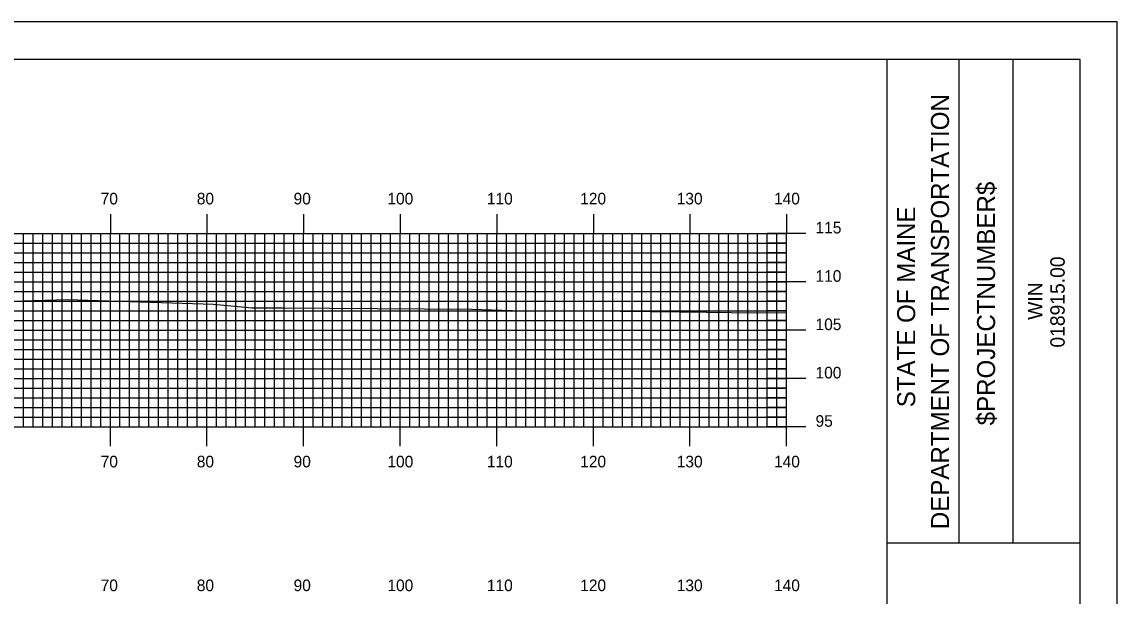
# Model space of a CAD drawing. Extents: x 1779106 to 1779449, y 442591 to 442811.
# Drawn here: x 1779332.2 to 1779445.5, y 442751.2 to 442810.5 of the extents above; entities that cross this region are included whole.
import ezdxf

# ---------------------------------------------------------------- set-up
doc = ezdxf.new("R2010")
doc.units = 0
for name, color, linetype in [('BORDER', 7, 'Continuous'), ('H_V ANNOTATION', 7, 'Continuous'), ('MAJOR', 7, 'Continuous'), ('MINOR', 7, 'Continuous'), ('PLOT BOUNDARY', 7, 'Continuous'), ('S_Roadway_Centerline', 7, 'Continuous')]:
    doc.layers.add(name, color=color, linetype=linetype)

msp = doc.modelspace()

# ---------------------------------------------------------------- linework, layer by layer
at = {"layer": 'BORDER'}
for p, q in [((1779421.73, 442596.67), (1779421.73, 442806.67)), ((1779429.19, 442756.66), (1779429.19, 442806.66)), ((1779434.78, 442756.66), (1779434.78, 442806.66)), ((1779421.73, 442756.65), (1779441.73, 442756.65))]:
    msp.add_line(p, q, dxfattribs=at)
msp.add_lwpolyline([(1779121.73, 442596.67), (1779441.73, 442596.67), (1779441.73, 442806.67), (1779121.73, 442806.67)], close=True, dxfattribs=at)
at = {"layer": 'MAJOR'}
for p, q in [((1779341.33, 442790.67), (1779341.33, 442788.67)), ((1779351.33, 442790.67), (1779351.33, 442788.67)), ((1779361.33, 442790.67), (1779361.33, 442788.67)), ((1779371.33, 442790.67), (1779371.33, 442788.67)), ((1779381.33, 442790.67), (1779381.33, 442788.67)), ((1779391.33, 442790.67), (1779391.33, 442788.67)), ((1779401.33, 442790.67), (1779401.33, 442788.67)), ((1779411.33, 442790.67), (1779411.33, 442788.67)), ((1779131.33, 442788.67), (1779411.33, 442788.67)), ((1779131.33, 442788.67), (1779411.33, 442788.67)), ((1779341.33, 442768.67), (1779341.33, 442788.67)), ((1779351.33, 442768.67), (1779351.33, 442788.67)), ((1779361.33, 442768.67), (1779361.33, 442788.67)), ((1779371.33, 442768.67), (1779371.33, 442788.67)), ((1779381.33, 442768.67), (1779381.33, 442788.67)), ((1779391.33, 442768.67), (1779391.33, 442788.67)), ((1779401.33, 442768.67), (1779401.33, 442788.67)), ((1779413.33, 442788.67), (1779409.33, 442788.67)), ((1779411.33, 442768.67), (1779411.33, 442788.67)), ((1779411.33, 442768.67), (1779411.33, 442788.67)), ((1779131.33, 442783.67), (1779411.33, 442783.67)), ((1779413.33, 442783.67), (1779409.33, 442783.67)), ((1779131.33, 442778.67), (1779411.33, 442778.67)), ((1779413.33, 442778.67), (1779409.33, 442778.67)), ((1779131.33, 442773.67), (1779411.33, 442773.67)), ((1779413.33, 442773.67), (1779409.33, 442773.67)), ((1779131.33, 442768.67), (1779411.33, 442768.67)), ((1779131.33, 442768.67), (1779411.33, 442768.67)), ((1779341.33, 442766.66), (1779341.33, 442768.67)), ((1779351.33, 442766.66), (1779351.33, 442768.67)), ((1779361.33, 442766.66), (1779361.33, 442768.67)), ((1779371.33, 442766.66), (1779371.33, 442768.67)), ((1779381.33, 442766.66), (1779381.33, 442768.67)), ((1779391.33, 442766.66), (1779391.33, 442768.67)), ((1779401.33, 442766.66), (1779401.33, 442768.67)), ((1779413.33, 442768.67), (1779409.33, 442768.67)), ((1779411.33, 442766.66), (1779411.33, 442768.67))]:
    msp.add_line(p, q, dxfattribs=at)
at = {"layer": 'MINOR'}
for p, q in [((1779332.33, 442768.67), (1779332.33, 442788.67)), ((1779333.33, 442768.67), (1779333.33, 442788.67)), ((1779334.33, 442768.67), (1779334.33, 442788.67)), ((1779335.33, 442768.67), (1779335.33, 442788.67)), ((1779336.33, 442768.67), (1779336.33, 442788.67)), ((1779337.33, 442768.67), (1779337.33, 442788.67)), ((1779338.33, 442768.67), (1779338.33, 442788.67)), ((1779339.33, 442768.67), (1779339.33, 442788.67)), ((1779340.33, 442768.67), (1779340.33, 442788.67)), ((1779342.33, 442768.67), (1779342.33, 442788.67)), ((1779343.33, 442768.67), (1779343.33, 442788.67)), ((1779344.33, 442768.67), (1779344.33, 442788.67)), ((1779345.33, 442768.67), (1779345.33, 442788.67)), ((1779346.33, 442768.67), (1779346.33, 442788.67)), ((1779347.33, 442768.67), (1779347.33, 442788.67)), ((1779348.33, 442768.67), (1779348.33, 442788.67)), ((1779349.33, 442768.67), (1779349.33, 442788.67)), ((1779350.33, 442768.67), (1779350.33, 442788.67)), ((1779352.33, 442768.67), (1779352.33, 442788.67)), ((1779353.33, 442768.67), (1779353.33, 442788.67)), ((1779354.33, 442768.67), (1779354.33, 442788.67)), ((1779355.33, 442768.67), (1779355.33, 442788.67)), ((1779356.33, 442768.67), (1779356.33, 442788.67)), ((1779357.33, 442768.67), (1779357.33, 442788.67)), ((1779358.33, 442768.67), (1779358.33, 442788.67)), ((1779359.33, 442768.67), (1779359.33, 442788.67)), ((1779360.33, 442768.67), (1779360.33, 442788.67)), ((1779362.33, 442768.67), (1779362.33, 442788.67)), ((1779363.33, 442768.67), (1779363.33, 442788.67)), ((1779364.33, 442768.67), (1779364.33, 442788.67)), ((1779365.33, 442768.67), (1779365.33, 442788.67)), ((1779366.33, 442768.67), (1779366.33, 442788.67)), ((1779367.33, 442768.67), (1779367.33, 442788.67)), ((1779368.33, 442768.67), (1779368.33, 442788.67)), ((1779369.33, 442768.67), (1779369.33, 442788.67)), ((1779370.33, 442768.67), (1779370.33, 442788.67)), ((1779372.33, 442768.67), (1779372.33, 442788.67)), ((1779373.33, 442768.67), (1779373.33, 442788.67)), ((1779374.33, 442768.67), (1779374.33, 442788.67)), ((1779375.33, 442768.67), (1779375.33, 442788.67)), ((1779376.33, 442768.67), (1779376.33, 442788.67)), ((1779377.33, 442768.67), (1779377.33, 442788.67)), ((1779378.33, 442768.67), (1779378.33, 442788.67)), ((1779379.33, 442768.67), (1779379.33, 442788.67)), ((1779380.33, 442768.67), (1779380.33, 442788.67)), ((1779382.33, 442768.67), (1779382.33, 442788.67)), ((1779383.33, 442768.67), (1779383.33, 442788.67)), ((1779384.33, 442768.67), (1779384.33, 442788.67)), ((1779385.33, 442768.67), (1779385.33, 442788.67)), ((1779386.33, 442768.67), (1779386.33, 442788.67)), ((1779387.33, 442768.67), (1779387.33, 442788.67)), ((1779388.33, 442768.67), (1779388.33, 442788.67)), ((1779389.33, 442768.67), (1779389.33, 442788.67)), ((1779390.33, 442768.67), (1779390.33, 442788.67)), ((1779392.33, 442768.67), (1779392.33, 442788.67)), ((1779393.33, 442768.67), (1779393.33, 442788.67)), ((1779394.33, 442768.67), (1779394.33, 442788.67)), ((1779395.33, 442768.67), (1779395.33, 442788.67)), ((1779396.33, 442768.67), (1779396.33, 442788.67)), ((1779397.33, 442768.67), (1779397.33, 442788.67)), ((1779398.33, 442768.67), (1779398.33, 442788.67)), ((1779399.33, 442768.67), (1779399.33, 442788.67)), ((1779400.33, 442768.67), (1779400.33, 442788.67)), ((1779402.33, 442768.67), (1779402.33, 442788.67)), ((1779403.33, 442768.67), (1779403.33, 442788.67)), ((1779404.33, 442768.67), (1779404.33, 442788.67)), ((1779405.33, 442768.67), (1779405.33, 442788.67)), ((1779406.33, 442768.67), (1779406.33, 442788.67)), ((1779407.33, 442768.67), (1779407.33, 442788.67)), ((1779408.33, 442768.67), (1779408.33, 442788.67)), ((1779409.33, 442768.67), (1779409.33, 442788.67)), ((1779410.33, 442768.67), (1779410.33, 442788.67)), ((1779131.33, 442787.67), (1779411.33, 442787.67)), ((1779411.33, 442787.67), (1779409.33, 442787.67)), ((1779131.33, 442786.67), (1779411.33, 442786.67)), ((1779411.33, 442786.67), (1779409.33, 442786.67)), ((1779131.33, 442785.67), (1779411.33, 442785.67)), ((1779411.33, 442785.67), (1779409.33, 442785.67)), ((1779131.33, 442784.67), (1779411.33, 442784.67)), ((1779411.33, 442784.67), (1779409.33, 442784.67)), ((1779131.33, 442782.67), (1779411.33, 442782.67)), ((1779411.33, 442782.67), (1779409.33, 442782.67)), ((1779131.33, 442781.67), (1779411.33, 442781.67)), ((1779131.33, 442780.67), (1779411.33, 442780.67)), ((1779411.33, 442781.67), (1779409.33, 442781.67)), ((1779411.33, 442780.67), (1779409.33, 442780.67)), ((1779131.33, 442779.67), (1779411.33, 442779.67)), ((1779411.33, 442779.67), (1779409.33, 442779.67)), ((1779131.33, 442777.67), (1779411.33, 442777.67)), ((1779411.33, 442777.67), (1779409.33, 442777.67)), ((1779131.33, 442776.67), (1779411.33, 442776.67)), ((1779411.33, 442776.67), (1779409.33, 442776.67)), ((1779131.33, 442775.67), (1779411.33, 442775.67)), ((1779411.33, 442775.67), (1779409.33, 442775.67)), ((1779131.33, 442774.67), (1779411.33, 442774.67)), ((1779411.33, 442774.67), (1779409.33, 442774.67)), ((1779131.33, 442772.67), (1779411.33, 442772.67)), ((1779411.33, 442772.67), (1779409.33, 442772.67)), ((1779131.33, 442771.67), (1779411.33, 442771.67)), ((1779411.33, 442771.67), (1779409.33, 442771.67)), ((1779131.33, 442770.67), (1779411.33, 442770.67)), ((1779411.33, 442770.67), (1779409.33, 442770.67)), ((1779131.33, 442769.67), (1779411.33, 442769.67)), ((1779411.33, 442769.67), (1779409.33, 442769.67))]:
    msp.add_line(p, q, dxfattribs=at)
at = {"layer": 'PLOT BOUNDARY'}
msp.add_lwpolyline([(1779105.54, 442590.55), (1779445.54, 442590.55), (1779445.54, 442810.55), (1779105.54, 442810.55)], close=True, dxfattribs=at)
at = {"layer": 'S_Roadway_Centerline'}
msp.add_lwpolyline([(1779327.75, 442781.55), (1779336.86, 442781.82), (1779352.01, 442781.35), (1779355.98, 442780.99), (1779359.15, 442780.96), (1779378.74, 442780.82), (1779382.95, 442780.71), (1779391.07, 442780.65), (1779400.33, 442780.57), (1779403.08, 442780.51), (1779405.6, 442780.5), (1779411.33, 442780.47)], dxfattribs=at)

# ---------------------------------------------------------------- texts
at = {"layer": 'BORDER'}
for s, height, p in [('DEPARTMENT OF TRANSPORTATION', 1.8635, (1779428.14, 442758.08)), ('$PROJECTNUMBER$', 1.8635, (1779432.91, 442768.82)), ('STATE OF MAINE', 1.8635, (1779424.64, 442770.69)), ('018915.00', 1.491, (1779440.12, 442776.86)), ('WIN', 1.491, (1779437.8, 442779.73))]:
    msp.add_text(s, height=height, rotation=90, dxfattribs=at).set_placement(p)
at = {"layer": 'H_V ANNOTATION'}
for s, p in [('70', (1779340.33, 442791.67)), ('80', (1779350.28, 442791.67)), ('90', (1779360.3, 442791.67)), ('100', (1779370.01, 442791.67)), ('110', (1779380.31, 442791.67)), ('120', (1779389.97, 442791.67)), ('130', (1779399.96, 442791.67)), ('140', (1779410.03, 442791.67)), ('115', (1779414.33, 442788.67)), ('110', (1779414.33, 442783.67)), ('105', (1779414.33, 442778.67)), ('100', (1779414.33, 442773.67)), ('95', (1779414.33, 442768.67)), ('70', (1779340.33, 442764.47)), ('80', (1779350.28, 442764.47)), ('90', (1779360.3, 442764.47)), ('100', (1779370.01, 442764.47)), ('110', (1779380.31, 442764.47)), ('120', (1779389.97, 442764.47)), ('130', (1779399.96, 442764.47)), ('140', (1779410.03, 442764.47)), ('70', (1779340.33, 442751.67)), ('80', (1779350.28, 442751.67)), ('90', (1779360.3, 442751.67)), ('100', (1779370.01, 442751.67)), ('110', (1779380.31, 442751.67)), ('120', (1779389.97, 442751.67)), ('130', (1779399.96, 442751.67)), ('140', (1779410.03, 442751.67))]:
    msp.add_text(s, height=1.2, dxfattribs=at).set_placement(p)

doc.saveas('drawing.dxf')
